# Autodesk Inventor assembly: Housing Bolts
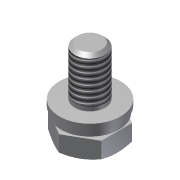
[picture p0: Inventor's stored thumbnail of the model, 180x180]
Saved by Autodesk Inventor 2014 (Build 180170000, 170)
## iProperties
Created: 2011-01
Part Number: Housing Bolts
Document SubType Name: Assembly
Designer: Beta-8540w
ClientObjectVersion: 1
Author: Beta-8540w
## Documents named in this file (4)
- C:\Inventor 2014 Essentials\Assemblies\Chapter 09\Design Accelerators\Bolted Connection c09-02.iam
- C:\Inventor 2014 Essentials\Content Center Files\en-US\ISO 8738\ISO 8738 - 4.ipt
- C:\Inventor 2014 Essentials\Content Center Files\en-US\DIN 128\DIN 128 - A4.ipt
- C:\Inventor 2014 Essentials\Content Center Files\en-US\ISO 4017\ISO 4017 - M4 x 8ISO.ipt
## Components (3 placed, 3 different names)
1. DIN EN 28738 4:1
2. DIN 128 A4:1
3. ISO 4017 M4 x 8:1
